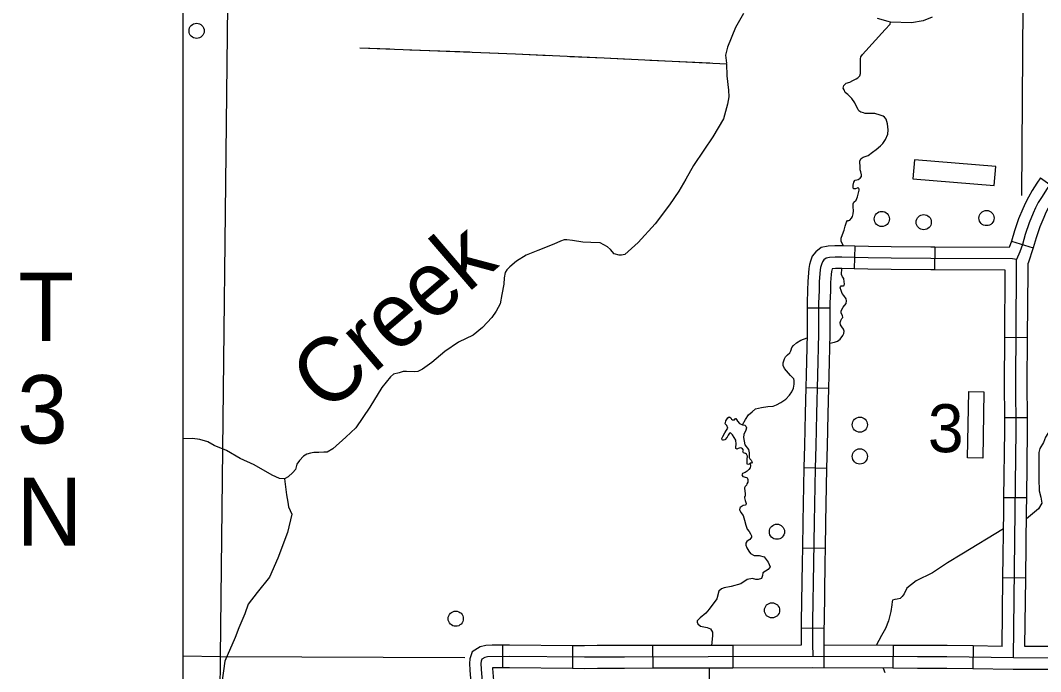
# Model space of a CAD drawing. Extents: x 1382482 to 1385815, y 1168351 to 1170484.
# Drawn here: x 1383389.5 to 1383658.5, y 1169071.9 to 1169243.6 of the extents above; entities that cross this region are included whole.
import ezdxf

# ---------------------------------------------------------------- set-up
doc = ezdxf.new("R2010")
doc.units = 0
for name, color, linetype in [('32', 7, 'Continuous'), ('35', 7, 'Continuous'), ('43', 7, 'Continuous'), ('5', 7, 'Continuous'), ('57', 7, 'Continuous'), ('8', 7, 'Continuous'), ('Default', 7, 'Continuous'), ('R_No Plot', 7, 'Continuous')]:
    doc.layers.add(name, color=color, linetype=linetype)

msp = doc.modelspace()

# ---------------------------------------------------------------- linework, layer by layer
at = {"layer": '32'}
for p, q in [((1383658.47, 1169202.04), (1383663.35, 1169198.55)), ((1383650.82, 1169185.39), (1383656.54, 1169183.58)), ((1383609.52, 1169184.04), (1383609.35, 1169178.04)), ((1383630.57, 1169183.82), (1383630.53, 1169177.82)), ((1383596.93, 1169167.81), (1383602.93, 1169167.81)), ((1383655.04, 1169159.9), (1383649.04, 1169159.94)), ((1383596.57, 1169146.77), (1383602.57, 1169146.61)), ((1383655, 1169138.81), (1383649, 1169138.79)), ((1383596.06, 1169125.66), (1383602.06, 1169125.5)), ((1383654.8, 1169117.65), (1383648.8, 1169117.72)), ((1383595.66, 1169104.51), (1383601.66, 1169104.42)), ((1383654.55, 1169096.53), (1383648.55, 1169096.6)), ((1383595.37, 1169083.36), (1383601.37, 1169083.33)), ((1383516.58, 1169078.84), (1383516.65, 1169072.84)), ((1383535.11, 1169078.67), (1383535.04, 1169072.67)), ((1383556.19, 1169078.72), (1383556.21, 1169072.72)), ((1383577.31, 1169078.77), (1383577.33, 1169072.77)), ((1383601.35, 1169078.83), (1383601.37, 1169072.83)), ((1383619.57, 1169078.74), (1383619.54, 1169072.74)), ((1383640.72, 1169078.61), (1383640.63, 1169072.61))]:
    msp.add_line(p, q, dxfattribs=at)
for points in [[(1383676.62, 1169239.07), (1383675.05, 1169231.55), (1383674, 1169226.81), (1383673.19, 1169224.84), (1383672.13, 1169222.01), (1383670.36, 1169218.07), (1383669.49, 1169216.04), (1383668.3, 1169212.93), (1383667.29, 1169210.46), (1383666.46, 1169208.79), (1383665.58, 1169207.2), (1383664.75, 1169205.89), (1383663.29, 1169203.66), (1383661.58, 1169201.23), (1383659.99, 1169199.01), (1383658.85, 1169197.17), (1383657.87, 1169195.53), (1383657.16, 1169194.19), (1383656.53, 1169192.75), (1383655.47, 1169190.21), (1383654.44, 1169187.16), (1383653.68, 1169184.48), (1383653, 1169182.54), (1383652.14, 1169180.57)], [(1383658.47, 1169202.04), (1383657.49, 1169200.67), (1383656.29, 1169198.73), (1383655.25, 1169197), (1383654.46, 1169195.49), (1383653.77, 1169193.93), (1383652.66, 1169191.27), (1383651.57, 1169188.05), (1383650.82, 1169185.39), (1383650.22, 1169183.68)], [(1383663.35, 1169198.55), (1383662.49, 1169197.35), (1383661.42, 1169195.61), (1383660.48, 1169194.05), (1383659.86, 1169192.88), (1383659.29, 1169191.57), (1383658.28, 1169189.15), (1383657.3, 1169186.27), (1383656.54, 1169183.58), (1383655.15, 1169179.6)], [(1383609.52, 1169184.04), (1383606.13, 1169184.14), (1383604.22, 1169184.14), (1383602.45, 1169184.02), (1383600.64, 1169183.67), (1383599.23, 1169182.59), (1383598.29, 1169181.41), (1383597.82, 1169180.11), (1383597.57, 1169179.17), (1383597.35, 1169178.19), (1383597.29, 1169177.01), (1383597.09, 1169174.76), (1383597.06, 1169172.43), (1383596.93, 1169169.11), (1383596.93, 1169167.81)], [(1383630.57, 1169183.82), (1383629.57, 1169183.82), (1383619.12, 1169183.87), (1383613.06, 1169183.94), (1383609.52, 1169184.04)], [(1383650.22, 1169183.68), (1383630.57, 1169183.82)], [(1383652.14, 1169180.57), (1383651.05, 1169180.67), (1383629.55, 1169180.82), (1383619.1, 1169180.87), (1383613, 1169180.94), (1383606.09, 1169181.14), (1383604.32, 1169181.14), (1383602.84, 1169181.04), (1383601.9, 1169180.86), (1383601.35, 1169180.43), (1383600.94, 1169179.93), (1383600.69, 1169179.22), (1383600.49, 1169178.46), (1383600.34, 1169177.78), (1383600.29, 1169176.8), (1383600.08, 1169174.6), (1383600.06, 1169172.36), (1383599.93, 1169169.05), (1383599.93, 1169160.89), (1383599.66, 1169150.01), (1383599.39, 1169139.85), (1383599.21, 1169131.42), (1383599.06, 1169125.54), (1383598.76, 1169111.25), (1383598.61, 1169100.55), (1383598.38, 1169085.05), (1383598.35, 1169079.3), (1383598.46, 1169075.84)], [(1383651.31, 1169075.45), (1383651.76, 1169114.27), (1383652.01, 1169135.45), (1383651.96, 1169147.77), (1383652.16, 1169177.54), (1383652.14, 1169180.57)], [(1383609.35, 1169178.04), (1383606.04, 1169178.14), (1383604.43, 1169178.14), (1383603.49, 1169178.07), (1383603.4, 1169177.75), (1383603.32, 1169177.38), (1383603.28, 1169176.58), (1383603.08, 1169174.45), (1383603.06, 1169172.28), (1383602.93, 1169168.99), (1383602.93, 1169167.81)], [(1383630.53, 1169177.82), (1383629.53, 1169177.82), (1383619.08, 1169177.87), (1383612.94, 1169177.94), (1383609.35, 1169178.04)], [(1383649.16, 1169177.68), (1383630.53, 1169177.82)], [(1383649.04, 1169159.94), (1383649.16, 1169177.68)], [(1383655.04, 1169159.9), (1383655.16, 1169177.54), (1383655.15, 1169179.6)], [(1383596.93, 1169167.81), (1383596.93, 1169160.93), (1383596.66, 1169150.09), (1383596.57, 1169146.77)], [(1383602.93, 1169167.81), (1383602.93, 1169160.86), (1383602.65, 1169149.94), (1383602.57, 1169146.61)], [(1383649, 1169138.79), (1383648.96, 1169147.78), (1383649.04, 1169159.94)], [(1383655, 1169138.81), (1383654.96, 1169147.77), (1383655.04, 1169159.9)], [(1383596.57, 1169146.77), (1383596.39, 1169139.92), (1383596.21, 1169131.49), (1383596.06, 1169125.66)], [(1383602.57, 1169146.61), (1383602.39, 1169139.78), (1383602.21, 1169131.35), (1383602.06, 1169125.5)], [(1383648.8, 1169117.72), (1383649.01, 1169135.47), (1383649, 1169138.79)], [(1383654.8, 1169117.65), (1383655.01, 1169135.44), (1383655, 1169138.81)], [(1383596.06, 1169125.66), (1383596.06, 1169125.61), (1383595.76, 1169111.31), (1383595.66, 1169104.51)], [(1383602.06, 1169125.5), (1383602.06, 1169125.47), (1383601.76, 1169111.2), (1383601.66, 1169104.42)], [(1383648.55, 1169096.6), (1383648.76, 1169114.31), (1383648.8, 1169117.72)], [(1383654.55, 1169096.53), (1383654.76, 1169114.24), (1383654.8, 1169117.65)], [(1383595.66, 1169104.51), (1383595.61, 1169100.59), (1383595.38, 1169085.08), (1383595.37, 1169083.36)], [(1383601.66, 1169104.42), (1383601.61, 1169100.51), (1383601.38, 1169085.02), (1383601.37, 1169083.33)], [(1383648.34, 1169078.49), (1383648.55, 1169096.6)], [(1383654.34, 1169078.44), (1383654.55, 1169096.53)], [(1383595.37, 1169083.36), (1383595.35, 1169078.83)], [(1383601.37, 1169083.33), (1383601.35, 1169078.83)], [(1383513.92, 1169078.81), (1383512.25, 1169078.78), (1383510.72, 1169078.4), (1383508.66, 1169077.09), (1383507.99, 1169075.21), (1383507.92, 1169073.98), (1383508, 1169072.27), (1383508.47, 1169066.91), (1383509.27, 1169057.25), (1383509.3, 1169056.83)], [(1383535.11, 1169078.67), (1383518.44, 1169078.86), (1383513.92, 1169078.81)], [(1383556.19, 1169078.72), (1383548.81, 1169078.7), (1383541.55, 1169078.7), (1383538.22, 1169078.63), (1383535.11, 1169078.67)], [(1383577.31, 1169078.77), (1383570.85, 1169078.75), (1383556.19, 1169078.72)], [(1383595.35, 1169078.83), (1383577.31, 1169078.77)], [(1383619.57, 1169078.74), (1383601.35, 1169078.83)], [(1383640.72, 1169078.61), (1383633.81, 1169078.71), (1383626.02, 1169078.71), (1383619.57, 1169078.74)], [(1383648.34, 1169078.49), (1383640.72, 1169078.61)], [(1383661.8, 1169078.44), (1383654.34, 1169078.44)], [(1383598.46, 1169075.84), (1383570.86, 1169075.75), (1383548.82, 1169075.7), (1383541.58, 1169075.7), (1383538.23, 1169075.63), (1383518.44, 1169075.86), (1383512.63, 1169075.79), (1383511.92, 1169075.61), (1383511.14, 1169075.11), (1383510.96, 1169074.61), (1383510.92, 1169073.97), (1383510.99, 1169072.47), (1383511.46, 1169067.16)], [(1383666.37, 1169075.44), (1383651.31, 1169075.45), (1383633.79, 1169075.71), (1383626.02, 1169075.71), (1383598.46, 1169075.84)], [(1383514, 1169072.81), (1383513.98, 1169072.81), (1383513.99, 1169072.68), (1383514.45, 1169067.42), (1383515.25, 1169057.74), (1383515.28, 1169057.32)], [(1383535.04, 1169072.67), (1383518.44, 1169072.86), (1383514, 1169072.81)], [(1383556.21, 1169072.72), (1383548.82, 1169072.7), (1383541.62, 1169072.7), (1383538.25, 1169072.63), (1383535.04, 1169072.67)], [(1383577.33, 1169072.77), (1383570.86, 1169072.75), (1383556.21, 1169072.72)], [(1383598.45, 1169072.84), (1383577.33, 1169072.77)], [(1383619.54, 1169072.74), (1383598.45, 1169072.84), (1383598.45, 1169072.84)], [(1383640.63, 1169072.61), (1383633.77, 1169072.71), (1383626.01, 1169072.71), (1383619.54, 1169072.74)], [(1383661.79, 1169072.44), (1383651.28, 1169072.45), (1383640.63, 1169072.61)]]:
    msp.add_lwpolyline(points, dxfattribs=at)
at = {"layer": '35'}
for points in [[(1383580.18, 1169245.43), (1383578.06, 1169241.69), (1383575.94, 1169236.51), (1383575.38, 1169234.43), (1383575.63, 1169232.28)], [(1383616.28, 1169210.48), (1383616.91, 1169211.14), (1383617.59, 1169212.17), (1383618.22, 1169213.61), (1383618.28, 1169214.75), (1383618.11, 1169216.28), (1383617.96, 1169216.96), (1383617.74, 1169217.5), (1383617.29, 1169218.02), (1383616.99, 1169218.31), (1383616.18, 1169218.61), (1383614.77, 1169219.05), (1383614.14, 1169219.07), (1383613.38, 1169219.07), (1383612.25, 1169219.07), (1383611.74, 1169219.17), (1383611.09, 1169219.35), (1383610.59, 1169219.73), (1383610.35, 1169220.1), (1383609.91, 1169220.85), (1383609.47, 1169221.87), (1383608.73, 1169223), (1383607.69, 1169224.01), (1383606.99, 1169224.59), (1383606.66, 1169225.24), (1383606.43, 1169225.75), (1383606.63, 1169226.4), (1383607.24, 1169226.99), (1383608.15, 1169227.31), (1383608.98, 1169227.72), (1383609.81, 1169228.15), (1383610.29, 1169228.4), (1383610.82, 1169228.93), (1383611, 1169229.54), (1383611.02, 1169230.37), (1383610.97, 1169232.01), (1383610.95, 1169233.4), (1383611.05, 1169233.95), (1383611.55, 1169234.58), (1383617.51, 1169241.15), (1383618.77, 1169242.56), (1383618.92, 1169243.07)], [(1383629.9, 1169244.47), (1383627.55, 1169243.42), (1383624.43, 1169242.92), (1383618.92, 1169243.07), (1383618.29, 1169243.27), (1383615.47, 1169244.12)], [(1383575.63, 1169232.15), (1383575.79, 1169228.96), (1383576.19, 1169225.17), (1383576.26, 1169223.43), (1383575.95, 1169221.45), (1383574.92, 1169217.66), (1383572.08, 1169212.84), (1383569.71, 1169209.36), (1383566.94, 1169205.33), (1383564.96, 1169201.69), (1383563.07, 1169198.53), (1383560.62, 1169194.97), (1383556.9, 1169189.95), (1383552.4, 1169184.97), (1383548.84, 1169181.81), (1383547.97, 1169181.65), (1383547.34, 1169181.65), (1383546.08, 1169182.05), (1383545.05, 1169183.15), (1383544.26, 1169183.87), (1383542.36, 1169184.89), (1383539.91, 1169184.97), (1383537.78, 1169185.13), (1383535.09, 1169185.53), (1383533.59, 1169185.68), (1383532.88, 1169185.68), (1383531.93, 1169185.37), (1383530.19, 1169184.58), (1383525.89, 1169182.92), (1383522.88, 1169181.65), (1383520.28, 1169180.07), (1383518.54, 1169178.57), (1383517.75, 1169177.78), (1383517.35, 1169177.07), (1383517.04, 1169175.72), (1383516.96, 1169174.06), (1383516.48, 1169171.3), (1383516.01, 1169168.85), (1383514.98, 1169166.87), (1383513.8, 1169165.21), (1383511.35, 1169162.6), (1383508.9, 1169160.55), (1383504.99, 1169158.77), (1383501.43, 1169156.24), (1383498.03, 1169153.39), (1383495.5, 1169151.57), (1383494.32, 1169151.02), (1383493.45, 1169150.94), (1383491.31, 1169151.02), (1383490.45, 1169151.02), (1383489.34, 1169150.63), (1383487.92, 1169150.31), (1383487.05, 1169149.6), (1383484.84, 1169146.75), (1383481.67, 1169141.61), (1383477.96, 1169136.16), (1383475.31, 1169133.67), (1383471.91, 1169130.59), (1383470.41, 1169129.72), (1383469.54, 1169129.72), (1383468.2, 1169129.64), (1383466.86, 1169129.64), (1383465.99, 1169129.48), (1383465.04, 1169129.16), (1383464.17, 1169128.69), (1383463.14, 1169127.5), (1383462.43, 1169126.56), (1383462.04, 1169125.13), (1383461.33, 1169124.34), (1383460.14, 1169123.24), (1383459.11, 1169122.68), (1383457.85, 1169122.76), (1383455.87, 1169123.63), (1383451.13, 1169126.4), (1383447.42, 1169128.06), (1383443.86, 1169130.19), (1383440.64, 1169131.46), (1383438.98, 1169132.48), (1383436.84, 1169133.04), (1383434.87, 1169133.35), (1383432.5, 1169133.28), (1383432.46, 1169133.27)], [(1383606.53, 1169184.14), (1383605.94, 1169185.29), (1383605.91, 1169185.74), (1383605.91, 1169186.17), (1383606.24, 1169187.13), (1383606.65, 1169188.24), (1383606.95, 1169189.33), (1383607.3, 1169190.34), (1383607.53, 1169190.77), (1383607.76, 1169190.84), (1383607.91, 1169190.84), (1383608.16, 1169190.89), (1383608.66, 1169191.4), (1383608.87, 1169191.88), (1383609.04, 1169192.61), (1383609.12, 1169193.39), (1383609.09, 1169194.38), (1383609.09, 1169194.88), (1383609.09, 1169195.21), (1383609.24, 1169195.64), (1383609.83, 1169196.2), (1383610.19, 1169197.09), (1383610.67, 1169198.83), (1383610.67, 1169199.06), (1383610.57, 1169199.26), (1383610.42, 1169199.42), (1383610.29, 1169199.44), (1383610.09, 1169199.31), (1383609.64, 1169199.14), (1383609.26, 1169199.14), (1383609.16, 1169199.19), (1383609.03, 1169199.52), (1383609.03, 1169200.12), (1383609.23, 1169200.93), (1383609.46, 1169201.38), (1383609.55, 1169201.48), (1383610.06, 1169201.51), (1383610.37, 1169201.58), (1383610.89, 1169201.97), (1383611.28, 1169202.42), (1383611.3, 1169202.85), (1383611.04, 1169203.66), (1383610.87, 1169204.18), (1383610.88, 1169204.61), (1383610.9, 1169205.22), (1383610.82, 1169206.05), (1383610.85, 1169206.56), (1383611.18, 1169207.12), (1383611.73, 1169207.52), (1383612.97, 1169207.95), (1383614.18, 1169208.81), (1383615.14, 1169209.56), (1383616.28, 1169210.48)], [(1383602.87, 1169158.49), (1383604.17, 1169158.75), (1383604.96, 1169158.98), (1383605.63, 1169159.53), (1383606.3, 1169160.47), (1383606.57, 1169161.05), (1383606.68, 1169161.66), (1383606.51, 1169162.19), (1383606.07, 1169162.74), (1383605.72, 1169163.3), (1383605.66, 1169163.88), (1383605.78, 1169164.47), (1383606.1, 1169164.93), (1383606.3, 1169165.23), (1383606.28, 1169165.72), (1383605.92, 1169166.36), (1383605.92, 1169167.01), (1383606.39, 1169168), (1383607.24, 1169168.93), (1383607.27, 1169169.63), (1383607.21, 1169170.13), (1383606.6, 1169171), (1383606.16, 1169171.56), (1383605.92, 1169172.32), (1383605.63, 1169173.07), (1383605.72, 1169173.34), (1383605.92, 1169173.6), (1383606.22, 1169173.6), (1383606.48, 1169173.6), (1383606.71, 1169173.66), (1383606.8, 1169174.15), (1383606.71, 1169174.68), (1383606.57, 1169175.56), (1383606.28, 1169175.99), (1383605.98, 1169176.61), (1383606.08, 1169178.14)], [(1383579.92, 1169136.97), (1383580.64, 1169138.36), (1383581.49, 1169139.54), (1383582.42, 1169140.39), (1383583.27, 1169141.11), (1383584.91, 1169141.53), (1383586.59, 1169141.75), (1383587.94, 1169141.89), (1383588.87, 1169142.21), (1383590.01, 1169142.85), (1383591.29, 1169143.74), (1383592.25, 1169144.71), (1383592.9, 1169145.67), (1383593.32, 1169146.63), (1383593.54, 1169147.66), (1383593.54, 1169148.59), (1383593.39, 1169149.09), (1383592.57, 1169149.95), (1383592, 1169150.55), (1383591.51, 1169151.19), (1383590.97, 1169151.76), (1383590.61, 1169152.58), (1383590.61, 1169153.3), (1383590.97, 1169154.33), (1383591.26, 1169154.86), (1383591.75, 1169155.36), (1383592.4, 1169155.93), (1383592.65, 1169156.46), (1383592.75, 1169156.75), (1383592.93, 1169157.28), (1383593.32, 1169157.89), (1383594.11, 1169158.53), (1383595.25, 1169159.24), (1383596.93, 1169159.83)], [(1383578.09, 1169132.9), (1383577.27, 1169134.32), (1383576.74, 1169134.86), (1383576.45, 1169134.72), (1383576.13, 1169134.22), (1383575.84, 1169133.65), (1383575.2, 1169133), (1383574.85, 1169132.86), (1383574.74, 1169132.86), (1383574.49, 1169133), (1383574.46, 1169133.33), (1383574.7, 1169133.82), (1383575.2, 1169134.82), (1383575.7, 1169135.5), (1383576.02, 1169136.07), (1383575.74, 1169136.78), (1383575.56, 1169136.93), (1383575.35, 1169137.17), (1383575.52, 1169137.92), (1383575.49, 1169137.96), (1383576.06, 1169138.78), (1383576.41, 1169139.03), (1383576.52, 1169138.99), (1383576.81, 1169138.81), (1383577.02, 1169138.39), (1383577.27, 1169138.28), (1383577.52, 1169138.21), (1383577.77, 1169138.24), (1383578.02, 1169138.56), (1383578.16, 1169138.6), (1383578.34, 1169138.35), (1383578.55, 1169137.89), (1383579.12, 1169137.28), (1383579.92, 1169136.97)], [(1383579.92, 1169136.97), (1383580.48, 1169136.82), (1383580.76, 1169136.6), (1383580.98, 1169136.18), (1383580.8, 1169135.5), (1383580.26, 1169134.36), (1383580.19, 1169133.57), (1383580.51, 1169131.65), (1383581.44, 1169130.44), (1383581.62, 1169129.58), (1383581.62, 1169128.91), (1383581.62, 1169128.3), (1383581.8, 1169127.94), (1383582.19, 1169127.59), (1383582.44, 1169127.09), (1383582.29, 1169126.84), (1383581.94, 1169126.84), (1383581.58, 1169126.45), (1383581.15, 1169126.55), (1383581.08, 1169126.8), (1383581.08, 1169127.12), (1383581.12, 1169127.87), (1383581.19, 1169128.69), (1383580.9, 1169129.19), (1383580.66, 1169129.37), (1383580.12, 1169129.55), (1383579.98, 1169129.9), (1383580.12, 1169130.26), (1383579.87, 1169130.62), (1383579.59, 1169130.76), (1383579.3, 1169130.87), (1383578.73, 1169130.69), (1383578.37, 1169130.51), (1383578.16, 1169130.72), (1383578.16, 1169131.08), (1383578.23, 1169131.79), (1383578.09, 1169132.9)], [(1383662.99, 1169137.25), (1383662.04, 1169136.55), (1383660.78, 1169135.34), (1383659.77, 1169133.67), (1383659.21, 1169132.26), (1383658.25, 1169130.67), (1383658, 1169129.66), (1383658, 1169122.69), (1383658.07, 1169119.5), (1383658.5, 1169117.89), (1383658.76, 1169116.23), (1383657.95, 1169114.81), (1383654.74, 1169112.16)], [(1383581.94, 1169126.84), (1383582.01, 1169126.09), (1383581.9, 1169125.63), (1383581.55, 1169125.16), (1383581.08, 1169124.74), (1383580.58, 1169124.38), (1383579.87, 1169124.06), (1383579.69, 1169123.77), (1383579.94, 1169123.31), (1383580.09, 1169123.28), (1383580.62, 1169123.13), (1383580.94, 1169123.03), (1383581.15, 1169122.92), (1383581.23, 1169122.78), (1383581.26, 1169122.53), (1383581.26, 1169122.24), (1383581.26, 1169121.78), (1383581.05, 1169121.39), (1383580.94, 1169121.03), (1383580.58, 1169120.67), (1383580.41, 1169120.32), (1383580.41, 1169120.07), (1383580.48, 1169119.64), (1383580.62, 1169118.68), (1383580.55, 1169118.11), (1383580.44, 1169117.93), (1383580.41, 1169117.68), (1383580.48, 1169117.32), (1383580.55, 1169116.97), (1383580.76, 1169116.47), (1383580.83, 1169116.18), (1383580.8, 1169115.86), (1383580.8, 1169115.83), (1383580.58, 1169115.72), (1383580.05, 1169115.65), (1383579.23, 1169115.15), (1383579.16, 1169114.93), (1383579.12, 1169114.51), (1383579.16, 1169114.47), (1383579.48, 1169113.79), (1383580.05, 1169113.02), (1383580.37, 1169111.77), (1383580.76, 1169110.49), (1383581.11, 1169109.45), (1383581.61, 1169108.77), (1383581.97, 1169108.17), (1383582.22, 1169107.67), (1383582.22, 1169107.35), (1383582.04, 1169107.03), (1383581.8, 1169106.71), (1383581.37, 1169106.39), (1383581.05, 1169106.14), (1383580.8, 1169105.75), (1383580.8, 1169105.18), (1383581.05, 1169104.46), (1383581.55, 1169103.61), (1383581.97, 1169103)], [(1383459.11, 1169122.68), (1383459.71, 1169118.51), (1383460.01, 1169116.53), (1383460.22, 1169115.29), (1383461.06, 1169113.35), (1383459.93, 1169108.56), (1383457.43, 1169101.73), (1383455.16, 1169096.8), (1383451.97, 1169092.72), (1383449.56, 1169089.64), (1383448.7, 1169087.11), (1383447.08, 1169083.38), (1383446.18, 1169080.85), (1383443.44, 1169074.62), (1383442.6, 1169068.89)], [(1383648.7, 1169109.54), (1383637.68, 1169102.83), (1383633.92, 1169100.57), (1383629.93, 1169097.92), (1383625.71, 1169095.76), (1383623.25, 1169093.82), (1383622.54, 1169092.36), (1383621.99, 1169091.7), (1383621.47, 1169091.17), (1383620.64, 1169090.94), (1383620, 1169090.87), (1383619.46, 1169090.71), (1383619.32, 1169090.37), (1383619.21, 1169089.49), (1383619.03, 1169087.74), (1383618.41, 1169085.25)], [(1383581.97, 1169103), (1383582.94, 1169102.51), (1383583.86, 1169102.51), (1383584.29, 1169102.51), (1383585.57, 1169102.08), (1383586.64, 1169100.73), (1383587.21, 1169099.52), (1383586.64, 1169098.81), (1383585.22, 1169097.88), (1383585.14, 1169097.24), (1383584.93, 1169096.45), (1383584, 1169096.17), (1383583.36, 1169096.17), (1383582.51, 1169096.45), (1383581.15, 1169096.17), (1383579.44, 1169095.03), (1383576.88, 1169094.31), (1383575.03, 1169093.96), (1383574.32, 1169093.69), (1383573.67, 1169093.03), (1383573.1, 1169091.03), (1383571.11, 1169088.33), (1383570.18, 1169087.26), (1383568.75, 1169086.04), (1383567.97, 1169085.26), (1383567.91, 1169084.85), (1383568.07, 1169084.41), (1383568.83, 1169083.86), (1383570.54, 1169083.48), (1383571.45, 1169083.12), (1383571.98, 1169082.25), (1383571.98, 1169081.31), (1383571.72, 1169078.76)], [(1383618.41, 1169085.25), (1383617.55, 1169083.2), (1383616.57, 1169081.35), (1383615.14, 1169078.76)], [(1383571.08, 1169072.75), (1383571.08, 1169067.73), (1383570.77, 1169065.82), (1383569.24, 1169063.06), (1383565.59, 1169058.2), (1383564.86, 1169056.42), (1383563.5, 1169052.88), (1383562.12, 1169048.36), (1383562.35, 1169046.52), (1383562.28, 1169044.15), (1383561.51, 1169041.93)], [(1383616.93, 1169072.75), (1383617.45, 1169071.66)]]:
    msp.add_lwpolyline(points, dxfattribs=at)
at = {"layer": '43'}
for points in [[(1383479, 1169236.35), (1383520.02, 1169234.8), (1383543.4, 1169233.67), (1383575.63, 1169232.15)], [(1383479, 1169236.35), (1383486.92, 1169236.05)], [(1383492.19, 1169235.85), (1383508.02, 1169235.26)], [(1383513.3, 1169235.06), (1383520.02, 1169234.8), (1383529.12, 1169234.36)], [(1383534.4, 1169234.1), (1383543.4, 1169233.67), (1383550.22, 1169233.35)], [(1383555.49, 1169233.1), (1383571.31, 1169232.35)]]:
    msp.add_lwpolyline(points, dxfattribs=at)
at = {"layer": '5'}
for points in [[(1383654.02, 1169285.12), (1383653.46, 1169197.36)], [(1383442.15, 1169075.79), (1383441.44, 1168987.13)], [(1383506.7, 1169075.47), (1383442.15, 1169075.79)]]:
    msp.add_lwpolyline(points, dxfattribs=at)
at = {"layer": '57'}
for p, q in [((1383625.21, 1169206.81), (1383624.8, 1169201.83)), ((1383646.64, 1169205.04), (1383625.21, 1169206.81)), ((1383646.23, 1169200.06), (1383646.64, 1169205.04)), ((1383624.8, 1169201.83), (1383646.23, 1169200.06))]:
    msp.add_line(p, q, dxfattribs=at)
at = {"layer": '8'}
msp.add_lwpolyline([(1383444.43, 1169271.16), (1383442.15, 1169075.79), (1383432.46, 1169075.93)], dxfattribs=at)
at = {"layer": 'Default'}
msp.add_lwpolyline([(1383639.54, 1169145.7), (1383643.54, 1169145.62), (1383643.21, 1169128.12), (1383639.21, 1169128.2)], close=True, dxfattribs=at)
for centre in [(1383435.98, 1169240.81), (1383644.22, 1169191.45), (1383616.6, 1169191.21), (1383627.66, 1169190.36), (1383610.83, 1169136.97), (1383610.81, 1169128.6), (1383588.96, 1169108.74), (1383587.67, 1169088.01), (1383504.29, 1169085.81)]:
    msp.add_circle(centre, 2, dxfattribs=at)
at = {"layer": 'R_No Plot'}
msp.add_lwpolyline([(1383432.46, 1169579.7), (1384939.88, 1169579.7), (1384939.88, 1168702.36), (1383432.46, 1168702.36)], close=True, dxfattribs=at)

# ---------------------------------------------------------------- texts
at = {"layer": '35'}
msp.add_text('Creek', height=16.896, rotation=40.6157, dxfattribs=at).set_placement((1383470.22, 1169139.65))
at = {"layer": 'Default'}
for s, height, p in [('T', 18, (1383388.99, 1169159.03)), ('3', 18, (1383388.65, 1169132.03)), ('3', 12.67, (1383628.75, 1169129.7)), ('N', 18, (1383388.49, 1169105.03))]:
    msp.add_text(s, height=height, dxfattribs=at).set_placement(p)

doc.saveas('drawing.dxf')
